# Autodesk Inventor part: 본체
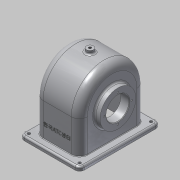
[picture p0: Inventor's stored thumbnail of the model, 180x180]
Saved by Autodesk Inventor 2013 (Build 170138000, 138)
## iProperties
Created: 2016-01
Part Number: 본체
Material: 알루미늄 6061
Document SubType Name: Modeling
Designer: Administrator
Density: 2.71 g/cm^3
Mass: 805.448 g
Surface Area: 985.542 cm^2
Volume: 297.213 cm^3
Author: Administrator
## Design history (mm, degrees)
sketch "스케치1"
  geometry: L1 (-57, 0)-(-57, -57); L2 (57, 0)-(57, -57); L3 (-57, -57)-(57, -57); A1 r 57 centre (0, 0) between (57, 0) and (-57, 0); 1 further point
  constraints: 6 end point, 2 point on circle, 2 tangent, 1 centre point, 1 coincident, 1 parallel, 1 perpendicular, 1 vertical
extrude "돌출1" new body sketch "스케치1" stored distance "d4" = 77; taper "d5" = 0 deg
sketch "스케치2"
  geometry: L1 (6, -6)-(71, -6) reference; L2 (71, -6)-(71, -108) reference; L3 (71, -108)-(6, -108) reference; L4 (6, -108)-(6, -6) reference; L5 (-13.5, 13)-(90.5, 13); L6 (90.5, 13)-(90.5, -127); L7 (90.5, -127)-(-13.5, -127); L8 (-13.5, -127)-(-13.5, 13); 3 further points
  constraints: 8 end point, 2 midpoint, 2 parallel, 1 horizontal, 1 horizontal alignment, 1 perpendicular, 1 vertical alignment
extrude "돌출2" join sketch "스케치2" distance "d10" = 7; taper "d11" = 0 deg
sketch "스케치3"
  geometry: 2 further points
hole "구멍1" sketch "스케치3" at (-82.5, 5) diameter "d14" = 5; stored, may be unused: countersink angle "d18" = 90 deg, drill point angle "d20" = 118 deg; dims "d15" = 6, "d16" = 4, "d17" = 2, "d19" = 8
sketch "스케치4"
  geometry: L1 (64, 70)-(64, -70) reference; C1 r 31 at (4, 0)
  constraints: 1 centre point
extrude "돌출3" join sketch "스케치4" distance "d23" = 10; taper "d24" = 0 deg
sketch "스케치7"
  geometry: L1 (-51, 0)-(-51, -97.929); L2 (-51, -97.929)-(51, -97.929); L3 (51, -97.929)-(51, 0); A1 r 51 centre (0, 0) between (51, 0) and (-51, 0); 1 further point
  constraints: 6 end point, 2 point on circle, 2 tangent, 1 centre point, 1 coincident, 1 perpendicular, 1 vertical
extrude "돌출5" cut sketch "스케치7" stored distance "d37" = 67; taper "d38" = 0 deg
node "작업 평면2"
sketch "스케치8"
  geometry: C1 r 6 at (38.5, -57); 1 further point
  constraints: 1 centre point, 1 coincident
  dimensions: "d40" = 12 diameter of C1
extrude "돌출6" join sketch "스케치8" stored distance "d41" = 67; taper "d42" = 0 deg
sketch "스케치9"
  geometry: C1 r 6 at (0, 0) reference; 1 further point
  constraints: 1 coincident
hole "구멍3" sketch "스케치9" at (0, 0) diameter "d43" = 4.459; stored, may be unused: countersink angle "d47" = 90 deg, drill point angle "d49" = 118 deg; dims "d44" = 18, "d45" = 4, "d46" = 2, "d48" = 20
sketch "스케치10"
  geometry: L1 (33.5, 0)-(33.5, 51) reference; L2 (33.5, 0)-(33.5, -64) reference; L3 (33.5, -4)-(17.5, -4); L4 (-33.5, -64)-(33.5, -64) reference; L5 (17.5, -4)-(17.5, 24); L6 (17.5, 24)-(33.5, 37.426); 1 further point
  constraints: 6 end point, 2 perpendicular, 2 point on line
revolve "회전1" sketch "스케치10" stored, may be unused: angle "d53" = 90 deg
sketch "스케치11"
  geometry: L1 (38.5, 0)-(38.5, 57) reference; L2 (38.5, 0)-(38.5, -57) reference; L3 (36.929, -4)-(35.5, -4); L4 (-33.5, -64)-(33.5, -64) reference; L5 (36.929, -4)-(38.5, -4); L6 (35.5, 32.577)-(35.5, -4); L7 (17.5, 24)-(33.5, 37.426) reference; L8 (35.5, 32.577)-(38.5, 35.094); L9 (38.5, 35.094)-(38.5, -4); 1 further point
  constraints: 10 end point, 3 perpendicular, 2 point on line, 1 collinear, 1 parallel
revolve "회전2" sketch "스케치11" stored, may be unused: angle "d59" = 90 deg
sketch "스케치12"
  geometry: C1 r 31 at (0, 0) reference; 2 further points
  constraints: 1 coincident
hole "구멍4" sketch "스케치12" at (0, 0) diameter "d60" = 40; stored, may be unused: countersink angle "d64" = 90 deg, drill point angle "d66" = 0 deg; dims "d61" = 18, "d62" = 4, "d63" = 2, "d65" = 20
sketch "스케치14"
  geometry: 2 further points
hole "구멍5" sketch "스케치14" at (28, 0) diameter "d74" = 2.459; stored, may be unused: countersink angle "d78" = 90 deg, drill point angle "d80" = 118 deg; dims "d75" = 7, "d76" = 4, "d77" = 2, "d79" = 9
sketch "스케치15"
  geometry: 2 further points
hole "구멍6" sketch "스케치15" at (-24, 0) diameter "d85" = 2.459; stored, may be unused: countersink angle "d89" = 90 deg, drill point angle "d91" = 118 deg; dims "d86" = 6, "d87" = 4, "d88" = 2, "d90" = 8
sketch "스케치16"
  geometry: L1 (77, 0)-(0, 0) reference; L2 (90.5, -64)-(-13.5, -64) reference; 3 further points
  constraints: 1 midpoint, 1 vertical alignment, 1 other
feature "엠보싱1" sketch "스케치16" dims "d96" = 0.5, "d97" = 0
chamfer "모따기1" distance "d98" = 1; stored, may be unused: second distance "d99" = 2, angle "d100" = 45 deg
fillet "모깎기2" dims "d101" = 14, "d103" = 8, "d104" = 9, "d105" = 3, "d106" = 1
node "솔리드1"
mirror "대칭1"
mirror "대칭2"
pattern_circular "원형 패턴1" dims angle "d82" = 360 deg
pattern_circular "원형 패턴2" dims angle "d93" = 360 deg
other parameters: "d39" = -127
